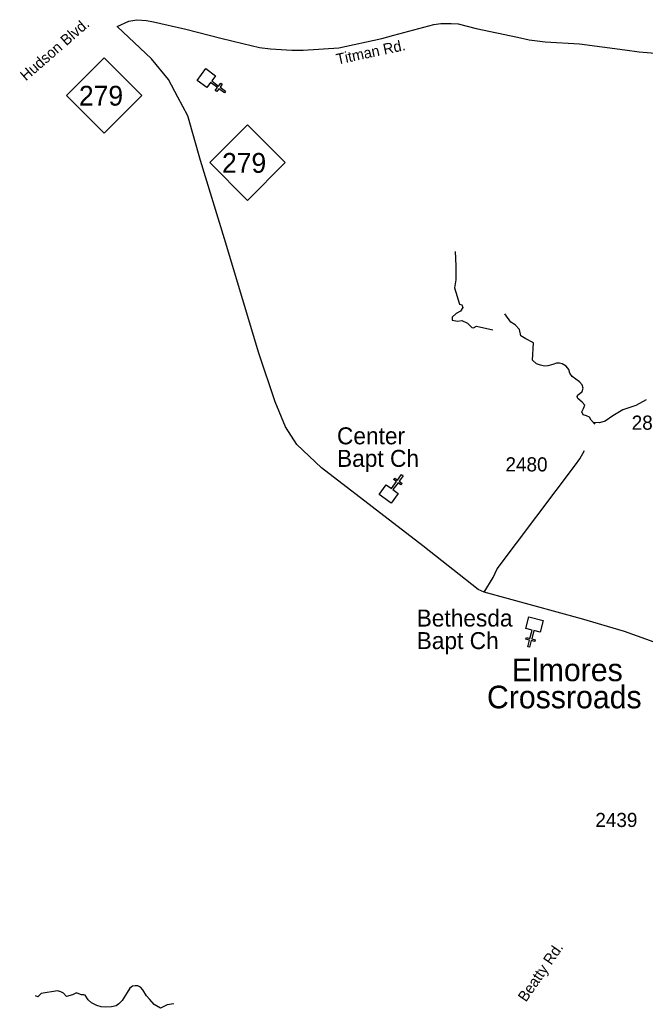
# Model space of a CAD drawing. Extents: x 1364363 to 1407445, y 538563 to 573342.
# Drawn here: x 1366839 to 1372368, y 539527 to 548262 of the extents above; entities that cross this region are included whole.
import ezdxf

# ---------------------------------------------------------------- set-up
doc = ezdxf.new("R2010")
doc.units = 0
for name, color, linetype in [('Exist Civil Demographics Community Label', 7, 'Continuous'), ('Exist Cultural Church CELL', 7, 'Continuous'), ('Exist Cultural Church with Cemetery Label', 7, 'Continuous'), ('Exist Hydrographic Creek Single Shore', 7, 'Continuous'), ('Exist Hydrographic Pond Under 1500 Sq Ft', 7, 'Continuous'), ('Exist Road Primary NC Attributed', 7, 'Continuous'), ('Exist Road Primary NC Shield CELL', 7, 'Continuous'), ('Exist Road Primary NC Shield Number Label', 7, 'Continuous'), ('Exist Road Secondary Type 51 Attributed', 7, 'Continuous'), ('Exist Road Secondary Type 51 Label', 7, 'Continuous'), ('Exist Road Secondary Type 51 Number Label', 7, 'Continuous')]:
    doc.layers.add(name, color=color, linetype=linetype)

msp = doc.modelspace()

# ---------------------------------------------------------------- linework, layer by layer
at = {"layer": 'Exist Cultural Church CELL'}
for points in [[(1368570.1, 547766.9), (1368536, 547721.3), (1368596.9, 547675.6), (1368616.1, 547701.2), (1368628.9, 547691.7), (1368609.7, 547666.1), (1368657.8, 547630), (1368648.2, 547617.2), (1368600.1, 547653.2), (1368580.9, 547627.6), (1368568.1, 547637.2), (1368587.3, 547662.8), (1368526.4, 547708.5), (1368491.7, 547662.4), (1368406.5, 547726.3), (1368484.9, 547830.8)], [(1370079.3, 544152.4), (1370125.4, 544119.1), (1370170.1, 544180.7), (1370144.2, 544199.5), (1370153.6, 544212.4), (1370179.5, 544193.6), (1370214.8, 544242.3), (1370227.8, 544232.9), (1370192.5, 544184.2), (1370218.4, 544165.4), (1370209, 544152.5), (1370183.1, 544171.3), (1370138.4, 544109.7), (1370185, 544075.7), (1370122.4, 543989.6), (1370016.7, 544066.3)], [(1371439.2, 542850.8), (1371384.1, 542865.1), (1371364.8, 542791.4), (1371395.8, 542783.3), (1371391.7, 542767.8), (1371360.8, 542775.9), (1371345.5, 542717.8), (1371330, 542721.8), (1371345.3, 542780), (1371314.3, 542788.1), (1371318.4, 542803.6), (1371349.3, 542795.5), (1371368.6, 542869.1), (1371312.8, 542883.8), (1371339.8, 542986.8), (1371466.1, 542953.7)]]:
    msp.add_lwpolyline(points, close=True, dxfattribs=at)
at = {"layer": 'Exist Hydrographic Creek Single Shore'}
for points in [[(1372375.8, 544902.6), (1372284.6, 544854.1), (1372170.5, 544814.1), (1372082.1, 544762.7), (1372013.7, 544714.2), (1371965.2, 544700), (1371913.9, 544702.8), (1371924.2, 544689.7), (1371890.9, 544724.9), (1371875.4, 544749), (1371847.7, 544761.9), (1371819.9, 544770.6), (1371808.4, 544796.3), (1371823, 544826.4), (1371833.6, 544855.7), (1371810.2, 544882.4), (1371772.8, 544915.1), (1371767.2, 544931.7), (1371771.5, 544947.2), (1371787.7, 544956.7), (1371812.2, 544978.4), (1371818.7, 545006.1), (1371809.4, 545036.7), (1371785.9, 545063.5), (1371722.9, 545108.2), (1371701.4, 545139), (1371692.1, 545171.2), (1371670.7, 545199.5), (1371635.1, 545220.7), (1371611.2, 545227), (1371583.2, 545227.5), (1371551, 545215.9), (1371506.6, 545202.8), (1371476.7, 545201.8), (1371442.8, 545210.7), (1371407.1, 545222.9), (1371371.7, 545253.9), (1371379.2, 545406.2), (1371313.6, 545443.3), (1371267.9, 545469), (1371256.5, 545526.1), (1371219.5, 545566), (1371179.5, 545588.9), (1371128.5, 545663.7)], [(1368202.7, 539565.1), (1368142.9, 539556.6), (1368083.2, 539526.7), (1368027.8, 539560.9), (1367988.6, 539603.2), (1367959.3, 539635.8), (1367928.4, 539688.2), (1367906.8, 539712.4), (1367883.1, 539723.6), (1367859.1, 539725.7), (1367835, 539722.1), (1367812.7, 539704.4), (1367787.9, 539665.6), (1367744.4, 539594.2), (1367715.7, 539566.9), (1367691.3, 539549.3), (1367651.1, 539537.8), (1367601, 539534.8), (1367559.1, 539539.7), (1367519.3, 539550.3), (1367473.7, 539573.4), (1367444.3, 539600.3), (1367417.2, 539642.7), (1367405.1, 539646.2), (1367383.7, 539646.2), (1367362.4, 539654.8), (1367341.1, 539663.3), (1367307, 539646.2), (1367251.5, 539629.1), (1367227.5, 539658.8), (1367201.8, 539671.9), (1367171.9, 539680.4), (1367029.5, 539658.2), (1366998.8, 539627.5), (1366978.3, 539636)]]:
    msp.add_lwpolyline(points, dxfattribs=at)
at = {"layer": 'Exist Hydrographic Pond Under 1500 Sq Ft'}
msp.add_lwpolyline([(1370689.3, 546214.7), (1370695.3, 546087.1), (1370693.2, 545962.4), (1370683.3, 545894.2), (1370726.1, 545748.7), (1370746.1, 545743), (1370754.6, 545720.1), (1370734.7, 545685.9), (1370697.6, 545665.9), (1370660.5, 545634.5), (1370660.5, 545608.8), (1370709, 545597.4), (1370746.1, 545603.1), (1370797.4, 545580.3), (1370834.5, 545543.2), (1370851.6, 545540.3), (1370877.3, 545554.6), (1371019.8, 545523.2)], dxfattribs=at)
at = {"layer": 'Exist Road Primary NC Attributed'}
for points in [[(1370945.9, 543204.7), (1370892.2, 543227), (1370402.6, 543613), (1369505.6, 544303.5), (1369287.2, 544507.9), (1369189.5, 544664.4), (1369097, 544884.8), (1368953.3, 545317.2), (1368650, 546326.5), (1368436.1, 547019.6), (1368324.4, 547413.1), (1368235.3, 547577.2), (1368155.5, 547733.7), (1368003.4, 547916.3), (1367701.7, 548203.4)], [(1372561.4, 542719.1), (1372186, 542856), (1371803.5, 542967.4), (1370945.9, 543204.7)]]:
    msp.add_lwpolyline(points, dxfattribs=at)
at = {"layer": 'Exist Road Primary NC Shield CELL'}
for points in [[(1367253.4, 547593.3), (1367586.4, 547926.3), (1367919.4, 547593.3), (1367586.4, 547260.3)], [(1368518.1, 546999.4), (1368851.1, 547332.4), (1369184.1, 546999.4), (1368851.1, 546666.4)]]:
    msp.add_lwpolyline(points, close=True, dxfattribs=at)
at = {"layer": 'Exist Road Secondary Type 51 Attributed'}
for points in [[(1367701.7, 548203.4), (1367802.4, 548250.4), (1367875.1, 548262.2), (1367961.1, 548254.3), (1368022.1, 548242.7), (1368308.5, 548177.8), (1368615.7, 548098.7), (1368810.2, 548053.7), (1368959.7, 548017.1), (1369055.5, 548005), (1369245.6, 547993.1), (1369345.7, 547992.9), (1369660, 548015.3), (1370040.7, 548096.7), (1370147.1, 548126), (1370498.4, 548219.2), (1370562.2, 548229.8), (1370651.5, 548230.6), (1370715.5, 548224.8), (1370873.4, 548184.1), (1371238.2, 548107.3), (1371342, 548086), (1371483, 548067.4), (1371786.4, 548048.8), (1372188.2, 547995.5), (1372313.3, 547979.5), (1372917.5, 547929)], [(1370945.9, 543204.7), (1371023, 543334.6), (1371060.2, 543411.3), (1371752.6, 544329.3), (1371789.9, 544382.6), (1371832.2, 544455.7)]]:
    msp.add_lwpolyline(points, dxfattribs=at)

# ---------------------------------------------------------------- texts
at = {"layer": 'Exist Civil Demographics Community Label'}
for s, p in [('Elmores', (1371188.6, 542417.1)), ('Crossroads', (1370969.1, 542177.1))]:
    msp.add_text(s, height=200, dxfattribs=at).set_placement(p)
at = {"layer": 'Exist Cultural Church with Cemetery Label'}
for s, p in [('Center', (1369643.6, 544510.2)), ('Bapt Ch', (1369643.6, 544311)), ('Bethesda ', (1370347.9, 542899.7)), ('Bapt Ch', (1370347.9, 542700.5))]:
    msp.add_text(s, height=150, dxfattribs=at).set_placement(p)
at = {"layer": 'Exist Road Primary NC Shield Number Label'}
for p in [(1367362.6, 547503.5), (1368627.3, 546909.7)]:
    msp.add_text('279', height=175, dxfattribs=at).set_placement(p)
at = {"layer": 'Exist Road Secondary Type 51 Label'}
for s, rotation, p in [('Hudson Blvd.', 41.05908, (1366894, 547716.7)), ('Titman Rd.', 12.06501, (1369647.7, 547865.2)), ('Beatty Rd.', 55.60553, (1371314.1, 539575.7))]:
    msp.add_text(s, height=95, rotation=rotation, dxfattribs=at).set_placement(p)
at = {"layer": 'Exist Road Secondary Type 51 Number Label'}
for s, p in [('2819', (1372248.6, 544639.2)), ('2480', (1371133, 544270.6)), ('2439', (1371927.2, 541128.3))]:
    msp.add_text(s, height=125, dxfattribs=at).set_placement(p)

doc.saveas('drawing.dxf')
